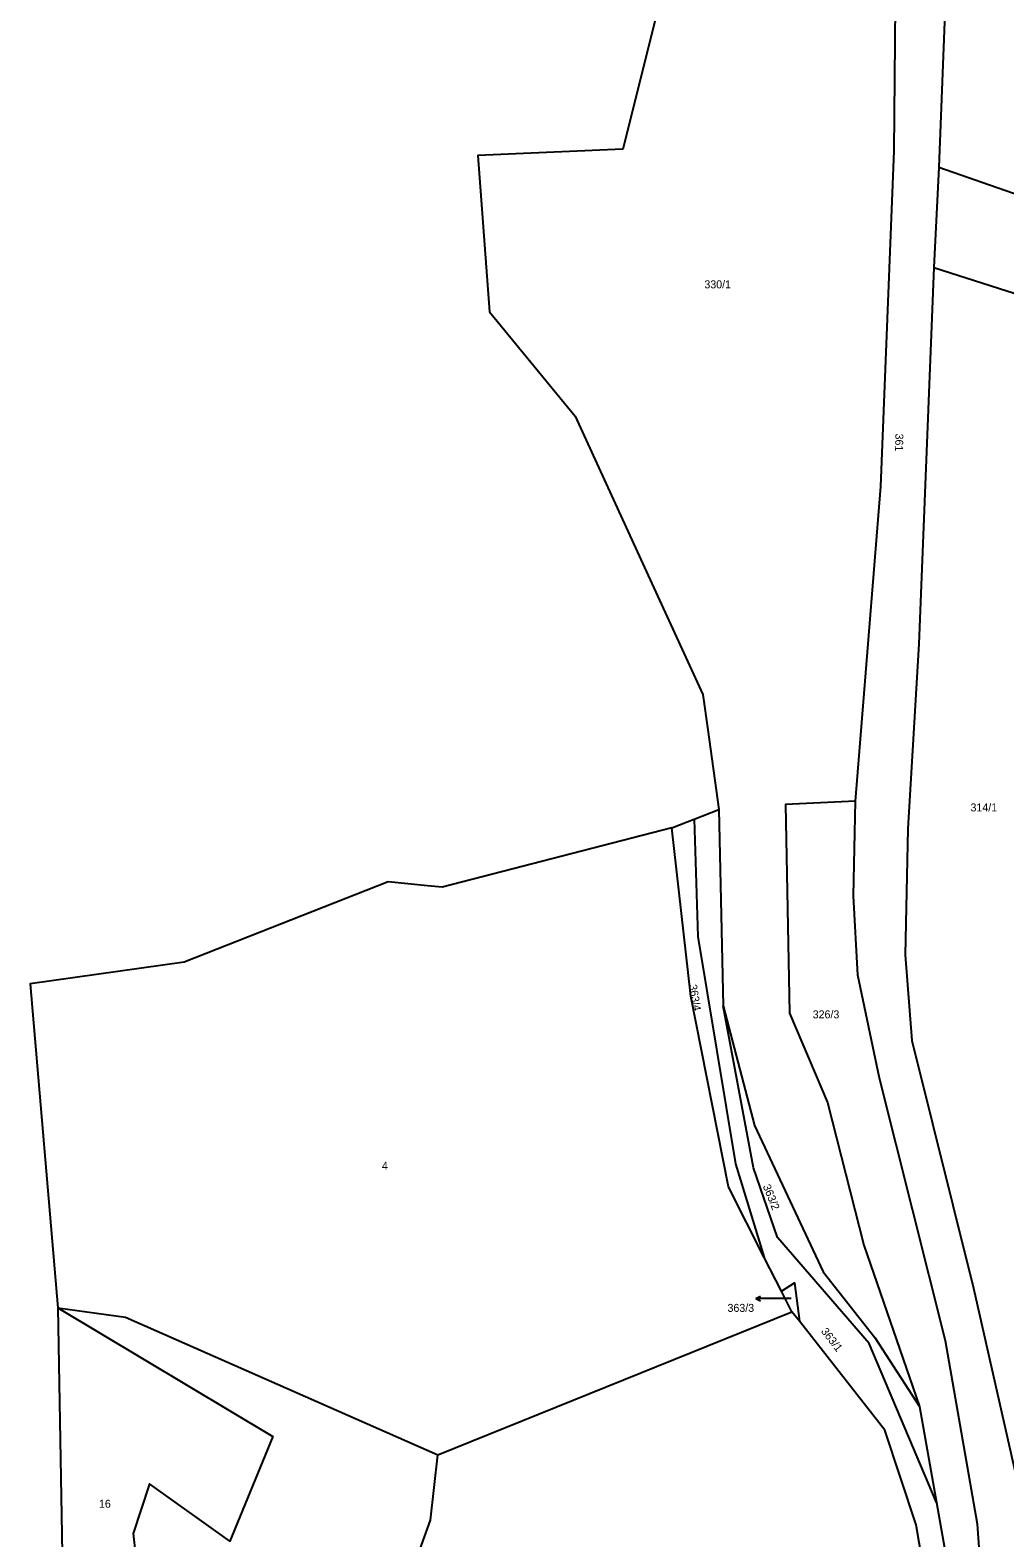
# Model space of a CAD drawing. Extents: x -880531 to -877616, y -1023932 to -1021350.
# Drawn here: x -878989.8 to -878781.4, y -1022286.3 to -1021964.1 of the extents above; entities that cross this region are included whole.
import ezdxf

# ---------------------------------------------------------------- set-up
doc = ezdxf.new("R2010")
doc.units = 0
for name, color, linetype in [('Hranice parcel', 7, 'Continuous'), ('Parcelní čísla', 7, 'Continuous'), ('Pop  PČ popisy', 7, 'Continuous')]:
    doc.layers.add(name, color=color, linetype=linetype)

msp = doc.modelspace()

# ---------------------------------------------------------------- linework, layer by layer
at = {"layer": 'Hranice parcel'}
for p, q in [((-878793.35, -1021937.32), (-878795.54, -1021993.32)), ((-878795.54, -1021993.32), (-878796.62, -1022014.79)), ((-878796.62, -1022014.79), (-878733.6, -1022035.04)), ((-878891.57, -1022024.26), (-878873.3, -1022046.58)), ((-878873.3, -1022046.58), (-878866.31, -1022061.8)), ((-878866.31, -1022061.8), (-878856.46, -1022083.24)), ((-878844.94, -1022113.64), (-878842.61, -1022130.65)), ((-878847.85, -1022132.72), (-878842.61, -1022130.65)), ((-878842.61, -1022130.65), (-878841.67, -1022172.58)), ((-878852.6, -1022134.6), (-878901.75, -1022147.24)), ((-878852.6, -1022134.6), (-878849.34, -1022133.31)), ((-878849.34, -1022133.31), (-878847.85, -1022132.72)), ((-878901.75, -1022147.24), (-878904.85, -1022146.93)), ((-878829.19, -1022233.59), (-878832.86, -1022226.38)), ((-878826.95, -1022238), (-878829.19, -1022233.59)), ((-878983.84, -1022237.15), (-878982.48, -1022315.78)), ((-878902.68, -1022268.58), (-878826.95, -1022238)), ((-878825.36, -1022240.03), (-878826.95, -1022238)), ((-878799.72, -1022258.24), (-878796.06, -1022278.81))]:
    msp.add_line(p, q, dxfattribs=at)
for points in [[(-878813.39, -1022128.85), (-878807.94, -1022061.6), (-878805.1, -1021989.82), (-878804.59, -1021935.28), (-878814.36, -1021883.57)], [(-878918.54, -1021921.07), (-878885.98, -1021937.26), (-878851.99, -1021945.01), (-878863.08, -1021989.53), (-878894.11, -1021990.84), (-878891.57, -1022024.26)], [(-878795.54, -1021993.32), (-878765.72, -1022003.77), (-878738.23, -1022017.29)], [(-878796.62, -1022014.79), (-878799.81, -1022095.23), (-878802.22, -1022134.81), (-878802.77, -1022161.7), (-878801.33, -1022180.04), (-878788.12, -1022233), (-878780.08, -1022268.54), (-878772.79, -1022301.21)], [(-878856.46, -1022083.24), (-878845.97, -1022106.08), (-878844.94, -1022113.64)], [(-878813.39, -1022128.85), (-878828.3, -1022129.56), (-878827.45, -1022174.15), (-878819.34, -1022193.26), (-878811.59, -1022223.8), (-878799.72, -1022258.24)], [(-878784.33, -1022324.92), (-878787.28, -1022283.42), (-878794.14, -1022244.21), (-878808.27, -1022188.07), (-878812.9, -1022166.07), (-878813.77, -1022149.07), (-878813.39, -1022128.85)], [(-878832.86, -1022226.38), (-878840.52, -1022211.3), (-878848.58, -1022170.57), (-878852.6, -1022134.6)], [(-878847.85, -1022132.72), (-878847.09, -1022157.81), (-878839.05, -1022206.42), (-878832.86, -1022226.38)], [(-878904.85, -1022146.93), (-878913.25, -1022146.1), (-878956.87, -1022163.29), (-878989.79, -1022167.92), (-878983.84, -1022237.15)], [(-878841.67, -1022172.58), (-878834.96, -1022198.2), (-878820.28, -1022229.45), (-878809.24, -1022243.5), (-878799.72, -1022258.24)], [(-878796.06, -1022278.81), (-878810.44, -1022244.79), (-878830.03, -1022222.15), (-878835.18, -1022207.26), (-878841.67, -1022172.58)], [(-878829.19, -1022233.59), (-878826.38, -1022231.84), (-878825.36, -1022240.03)], [(-878983.84, -1022237.15), (-878937.9, -1022264.69), (-878947.13, -1022287.08), (-878964.25, -1022274.82), (-878967.78, -1022285.4), (-878964.77, -1022312.19), (-878973.23, -1022312.29)], [(-878983.84, -1022237.15), (-878969.43, -1022239.13), (-878902.68, -1022268.58)], [(-878795.44, -1022312.88), (-878800.43, -1022283.55), (-878807.1, -1022263.29), (-878825.36, -1022240.03)], [(-878927.84, -1022348.34), (-878904.21, -1022282.53), (-878902.68, -1022268.58)], [(-878796.06, -1022278.81), (-878787.83, -1022325.15), (-878784.33, -1022324.92)]]:
    msp.add_lwpolyline(points, dxfattribs=at)
at = {"layer": 'Pop  PČ popisy'}
for p, q in [((-878834.691, -1022235.17), (-878833.69, -1022234.669)), ((-878831.69, -1022235.17), (-878834.691, -1022235.17)), ((-878834.691, -1022235.17), (-878833.69, -1022235.671)), ((-878827.09, -1022235.15), (-878831.69, -1022235.17))]:
    msp.add_line(p, q, dxfattribs=at)

# ---------------------------------------------------------------- texts
at = {"layer": 'Parcelní čísla'}
for s, p in [('330/1', (-878845.67, -1022019.24)), ('314/1', (-878788.79, -1022131.05)), ('326/3', (-878822.52, -1022175.29)), ('4', (-878914.6, -1022207.63)), ('363/3', (-878840.732, -1022238.028)), ('16', (-878975.08, -1022279.9))]:
    msp.add_text(s, height=1.7, dxfattribs=at).set_placement(p)
for s, rotation, p in [('361', 269, (-878804.839, -1022050.275)), ('363/4', 280, (-878848.987, -1022168.197)), ('363/2', 292, (-878833.218, -1022211.168)), ('363/1', 308, (-878820.849, -1022242.223))]:
    msp.add_text(s, height=1.7, rotation=rotation, dxfattribs=at).set_placement(p)

doc.saveas('drawing.dxf')
